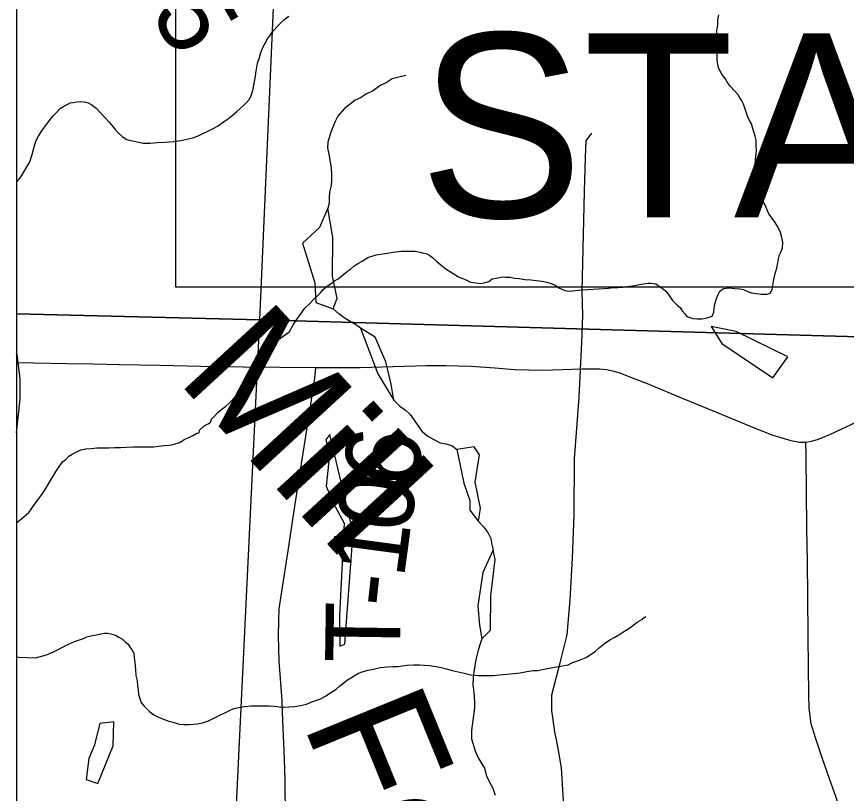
# Model space of a CAD drawing. Extents: x -6.1 to 38, y -7.7 to 22.
# Drawn here: x 2.1 to 2.73, y 16.715 to 17.306 of the extents above; entities that cross this region are included whole.
import ezdxf

# ---------------------------------------------------------------- set-up
doc = ezdxf.new("R2010")
doc.units = 0
for name, color, linetype in [('GM_X_Corporation', 7, 'Continuous'), ('GM_X_Minor_Lake', 7, 'Continuous'), ('GM_X_Minor_River', 7, 'Continuous'), ('GM_X_Minor_River_Text', 7, 'Continuous'), ('GM_X_State_Route', 7, 'Continuous'), ('GM_X_Township_Road', 7, 'Continuous'), ('GM_X_Township_Road_Text', 7, 'Continuous'), ('SH_Data', 7, 'Continuous'), ('SH_Text', 7, 'Continuous')]:
    doc.layers.add(name, color=color, linetype=linetype)

msp = doc.modelspace()

# ---------------------------------------------------------------- linework, layer by layer
at = {"layer": 'GM_X_Corporation'}
for points in [[(2.1, 20.09414), (2.1, 15.06368), (2.27273, 15.0594), (2.84159, 15.04746)], [(2.1, 19.36551), (2.1, 14.52316), (2.69973, 14.52546), (2.99532, 14.5306)]]:
    msp.add_lwpolyline(points, dxfattribs=at)
for points in [[(2.1, 18.08314), (2.1, 17.07982), (2.28477, 17.07512), (2.32853, 18.07616)], [(3.27494, 18.04606), (3.26971, 17.73075), (3.25731, 17.04745), (2.28477, 17.07512), (2.32853, 18.07616)], [(2.1, 17.07982), (2.1, 16.07221), (2.23638, 16.06946), (2.28477, 17.07512)], [(2.28477, 17.07512), (3.25731, 17.04745), (3.25716, 17.0301), (3.24834, 16.45211), (3.24267, 16.03673), (2.23638, 16.06946)]]:
    msp.add_lwpolyline(points, close=True, dxfattribs=at)
at = {"layer": 'GM_X_Minor_Lake'}
for points in [[(2.33637, 17.16011), (2.33002, 17.1453), (2.31723, 17.1335), (2.32644, 17.10322), (2.32727, 17.08844), (2.34051, 17.08357)], [(2.34051, 17.08357), (2.3435, 17.09154), (2.34002, 17.1082), (2.34025, 17.13776), (2.33637, 17.16011)], [(2.36136, 17.06887), (2.37438, 17.03406), (2.38656, 17.01402)], [(2.38656, 17.01402), (2.38462, 17.02614), (2.38038, 17.04318), (2.37235, 17.0621), (2.36136, 17.06887)], [(2.68601, 17.04709), (2.64663, 17.06626), (2.62772, 17.06997), (2.63572, 17.05712)], [(2.63572, 17.05712), (2.67438, 17.03113), (2.68601, 17.04709)], [(2.33795, 16.98805), (2.33495, 16.98387), (2.33765, 16.97251), (2.33512, 16.94863), (2.34047, 16.93614), (2.34885, 16.92064), (2.34541, 16.85051), (2.34553, 16.82701)], [(2.34553, 16.82701), (2.3493, 16.82855), (2.35569, 16.91346), (2.33795, 16.98805)], [(2.45086, 16.92181), (2.45232, 16.93205), (2.44845, 16.95174), (2.45175, 16.9726), (2.44756, 16.97865), (2.43435, 16.9767)], [(2.43435, 16.9767), (2.43976, 16.95095), (2.44436, 16.93771), (2.44439, 16.9305), (2.45086, 16.92181)], [(2.46192, 16.90026), (2.45407, 16.88317), (2.45041, 16.85776), (2.45162, 16.84299), (2.45355, 16.83276)], [(2.45355, 16.83276), (2.45994, 16.83923), (2.4602, 16.86538), (2.46346, 16.89306), (2.46192, 16.90026)], [(2.16333, 16.76829), (2.15888, 16.75122), (2.15477, 16.74173), (2.15296, 16.7258), (2.16166, 16.7228)], [(2.16166, 16.7228), (2.17324, 16.75128), (2.1739, 16.76947), (2.16333, 16.76829)]]:
    msp.add_lwpolyline(points, dxfattribs=at)
at = {"layer": 'GM_X_Minor_River'}
for points in [[(2.14607, 17.24083), (2.14873, 17.24124), (2.1514, 17.24089), (2.15444, 17.24015), (2.15712, 17.23866), (2.16057, 17.23603), (2.16365, 17.23264), (2.16673, 17.22925), (2.17058, 17.22511), (2.1729, 17.22247), (2.17483, 17.21983), (2.17714, 17.21719), (2.18021, 17.21456), (2.18366, 17.21231), (2.19624, 17.20939), (2.20156, 17.20945), (2.20687, 17.20988), (2.21257, 17.21032), (2.21979, 17.21077), (2.22472, 17.21158), (2.22928, 17.21238), (2.23382, 17.21357), (2.23799, 17.21513), (2.24139, 17.21669), (2.24517, 17.21862), (2.24933, 17.22057), (2.25311, 17.22251), (2.2565, 17.2252), (2.25989, 17.22752), (2.26366, 17.2306), (2.26705, 17.23329), (2.27006, 17.23598), (2.27269, 17.23829), (2.27495, 17.24059), (2.27682, 17.24289), (2.27831, 17.24557), (2.27941, 17.24938), (2.28012, 17.25357), (2.2812, 17.25891), (2.2819, 17.26424), (2.28297, 17.27033), (2.28444, 17.27453), (2.28553, 17.27834), (2.28701, 17.28216), (2.28887, 17.2856), (2.29073, 17.28866), (2.29298, 17.29172), (2.29522, 17.29517), (2.2986, 17.299), (2.30274, 17.30285), (2.30688, 17.30593)], [(2.61138, 17.07702), (2.61367, 17.07629), (2.61709, 17.07594), (2.62051, 17.07597), (2.62355, 17.07638), (2.6262, 17.07717), (2.62847, 17.07795), (2.62958, 17.08101), (2.63028, 17.08596), (2.63174, 17.09129), (2.63285, 17.09435), (2.63433, 17.09702), (2.63697, 17.09895), (2.64153, 17.09938), (2.64572, 17.09904), (2.64952, 17.09869), (2.65219, 17.09834), (2.65601, 17.09648), (2.6583, 17.09574), (2.66554, 17.09467), (2.66782, 17.09469), (2.6701, 17.09472), (2.67237, 17.0955), (2.67386, 17.09818), (2.67458, 17.10122), (2.67529, 17.1058), (2.67638, 17.11037), (2.67747, 17.11456), (2.67818, 17.11837), (2.67891, 17.12142), (2.67964, 17.12447), (2.68074, 17.12714), (2.68186, 17.12981), (2.68219, 17.134), (2.68138, 17.13779), (2.6802, 17.14158), (2.67825, 17.14575), (2.67631, 17.14915), (2.6736, 17.15292), (2.67128, 17.15632), (2.66933, 17.16049), (2.66699, 17.16579), (2.66502, 17.17223), (2.66264, 17.18057), (2.66143, 17.18626), (2.66101, 17.19006), (2.66097, 17.19348), (2.66131, 17.19653), (2.66166, 17.19957), (2.66199, 17.20338), (2.66194, 17.20794), (2.6619, 17.21174), (2.6611, 17.21478), (2.65991, 17.21895), (2.65833, 17.22426), (2.65639, 17.22728), (2.65522, 17.22993), (2.65443, 17.23258), (2.65325, 17.23599), (2.65208, 17.23902), (2.6509, 17.24167), (2.64936, 17.24394), (2.64819, 17.2462), (2.64242, 17.25261), (2.6401, 17.25563), (2.63855, 17.25828), (2.637, 17.26016), (2.63546, 17.26243), (2.63429, 17.2647), (2.63313, 17.26697), (2.63272, 17.26925), (2.6323, 17.27228), (2.63224, 17.27798), (2.63257, 17.28255), (2.63214, 17.28635), (2.6321, 17.28977), (2.63207, 17.29281), (2.63204, 17.29547), (2.63239, 17.29738), (2.63274, 17.30004), (2.63272, 17.30232), (2.63307, 17.30461), (2.63342, 17.30689)], [(2.39558, 17.26078), (2.39029, 17.25962), (2.38539, 17.25846), (2.38087, 17.25541), (2.37672, 17.2535), (2.37032, 17.24893), (2.36579, 17.24702), (2.36128, 17.24396), (2.35713, 17.24205), (2.34885, 17.23558), (2.34397, 17.22987), (2.34172, 17.22531), (2.33873, 17.21772), (2.3365, 17.21013), (2.33614, 17.20596), (2.3373, 17.20104), (2.33808, 17.19687), (2.33886, 17.19043), (2.33926, 17.18627), (2.33929, 17.18134), (2.33893, 17.17717), (2.33782, 17.17224), (2.33746, 17.16807), (2.33748, 17.1639), (2.33637, 17.16011)], [(2.1, 17.1799), (2.10002, 17.17992), (2.10302, 17.18337), (2.106, 17.18834), (2.11011, 17.19523), (2.11194, 17.20095), (2.11339, 17.20667), (2.11449, 17.21086), (2.11672, 17.21469), (2.11858, 17.21813), (2.12121, 17.22158), (2.1242, 17.22579), (2.12757, 17.23), (2.13057, 17.23308), (2.13321, 17.23576), (2.13584, 17.23769), (2.13849, 17.23886), (2.14076, 17.24002), (2.14304, 17.24042), (2.14607, 17.24083)], [(2.26539, 17.01579), (2.26727, 17.01733), (2.26877, 17.01925), (2.27026, 17.02154), (2.27175, 17.02422), (2.27361, 17.02766), (2.27548, 17.03034), (2.27735, 17.0334), (2.27921, 17.03684), (2.28183, 17.04067), (2.28482, 17.0445), (2.28857, 17.0491), (2.29232, 17.05332), (2.29607, 17.05754), (2.29984, 17.06062), (2.30286, 17.06293), (2.30549, 17.06486), (2.30738, 17.0664), (2.30998, 17.07137), (2.3126, 17.07519), (2.31597, 17.07979), (2.31896, 17.084), (2.32272, 17.08746), (2.32572, 17.09091), (2.32836, 17.09322), (2.33061, 17.09552), (2.33286, 17.09821), (2.33625, 17.1009), (2.33889, 17.10283), (2.34153, 17.10476), (2.34417, 17.1063), (2.35133, 17.11208), (2.35359, 17.11362), (2.35622, 17.11593), (2.35924, 17.11786), (2.36264, 17.11979), (2.36679, 17.1225), (2.37323, 17.12446), (2.37968, 17.12567), (2.38613, 17.12649), (2.39221, 17.12731), (2.39791, 17.12737), (2.40285, 17.12742), (2.40666, 17.1267), (2.40933, 17.12596), (2.41162, 17.12523), (2.41391, 17.12411), (2.41583, 17.12261), (2.41929, 17.1196), (2.42236, 17.11697), (2.42619, 17.11396), (2.43079, 17.11097), (2.43577, 17.10797), (2.44074, 17.10574), (2.44494, 17.10388), (2.44875, 17.10316), (2.45255, 17.10282), (2.45597, 17.10361), (2.45862, 17.1044), (2.46126, 17.10633), (2.46581, 17.10713), (2.46884, 17.10793), (2.47151, 17.10757), (2.47493, 17.1076), (2.47836, 17.10688), (2.48178, 17.10653), (2.48597, 17.10581), (2.49054, 17.10548), (2.49472, 17.10514), (2.49929, 17.10443), (2.50272, 17.1037), (2.50692, 17.1026), (2.50921, 17.10148), (2.5119, 17.09961), (2.51648, 17.09737), (2.51991, 17.09703), (2.52447, 17.09745), (2.52902, 17.09788), (2.53396, 17.09831), (2.54954, 17.09922), (2.55333, 17.09964), (2.55675, 17.09967), (2.56055, 17.10009), (2.56397, 17.10051), (2.56776, 17.10092), (2.57194, 17.10172), (2.57611, 17.10253), (2.5799, 17.10295), (2.58218, 17.10297), (2.58561, 17.10262), (2.58906, 17.09999), (2.59136, 17.0985), (2.59328, 17.097), (2.59521, 17.09435), (2.5983, 17.08982), (2.60176, 17.08643), (2.60407, 17.08456), (2.60562, 17.08191), (2.60754, 17.07965), (2.60909, 17.07776), (2.61138, 17.07702)], [(2.36136, 17.06887), (2.35757, 17.07151), (2.35341, 17.07377), (2.34886, 17.07678), (2.34469, 17.07979), (2.34051, 17.08357)], [(2.1, 16.92078), (2.10563, 16.92561), (2.1094, 16.92869), (2.11239, 16.9329), (2.11575, 16.9375), (2.11912, 16.94247), (2.12211, 16.94707), (2.12472, 16.95128), (2.12733, 16.95548), (2.12994, 16.96007), (2.13293, 16.96429), (2.13518, 16.96735), (2.13744, 16.96889), (2.13969, 16.97158), (2.14233, 16.97312), (2.14536, 16.97467), (2.14876, 16.97623), (2.15255, 16.97703), (2.15673, 16.97745), (2.1609, 16.97787), (2.16547, 16.97792), (2.17003, 16.97796), (2.17459, 16.97801), (2.17915, 16.97805), (2.18333, 16.97847), (2.18865, 16.97853), (2.19283, 16.97857), (2.19663, 16.97861), (2.20005, 16.97864), (2.20423, 16.97868), (2.20803, 16.9791), (2.21221, 16.97952), (2.216, 16.97994), (2.21904, 16.98035), (2.22131, 16.98113), (2.22396, 16.98192), (2.22736, 16.98423), (2.23076, 16.98579), (2.23379, 16.98734), (2.23681, 16.98889), (2.2387, 16.98929), (2.23906, 16.99119), (2.24244, 16.99465), (2.24547, 16.9962), (2.24735, 16.99736), (2.24809, 16.99965), (2.25034, 17.00195), (2.25297, 17.00464), (2.25598, 17.00733), (2.259, 17.00964), (2.26125, 17.01157), (2.26313, 17.01349), (2.26539, 17.01579)], [(2.38656, 17.01402), (2.39112, 17.00949), (2.39529, 17.00686), (2.39908, 17.00308), (2.40213, 16.99892), (2.40783, 16.99061), (2.41239, 16.98684), (2.41693, 16.98421), (2.42186, 16.98157), (2.42602, 16.98083), (2.43056, 16.97972), (2.43435, 16.9767)], [(2.45086, 16.92181), (2.45503, 16.91766), (2.45808, 16.9135), (2.46036, 16.90897), (2.46114, 16.90442), (2.46192, 16.90026)], [(2.33869, 16.79182), (2.34247, 16.79413), (2.34548, 16.79683), (2.34849, 16.79914), (2.3515, 16.80145), (2.35452, 16.80338), (2.35717, 16.80493), (2.35981, 16.80647), (2.36246, 16.80764), (2.36701, 16.80883), (2.37118, 16.80963), (2.37649, 16.81082), (2.3818, 16.81126), (2.38598, 16.81168), (2.38978, 16.81171), (2.39282, 16.81212), (2.39661, 16.81254), (2.40155, 16.81297), (2.40611, 16.81302), (2.40992, 16.81267), (2.41372, 16.81233), (2.41867, 16.81162), (2.42249, 16.8109), (2.42668, 16.8098), (2.43087, 16.8087), (2.43545, 16.80761), (2.44002, 16.80651), (2.44498, 16.80542), (2.45031, 16.80471), (2.45601, 16.80477), (2.46209, 16.80483), (2.48259, 16.80694), (2.48753, 16.80774), (2.49246, 16.80855), (2.49588, 16.80859), (2.49816, 16.80899), (2.50195, 16.80979), (2.50612, 16.81059), (2.50991, 16.81139), (2.51485, 16.8122), (2.51902, 16.813), (2.52242, 16.81455), (2.52772, 16.81651), (2.53264, 16.81846), (2.53604, 16.82077), (2.53943, 16.82309), (2.54282, 16.82616), (2.54658, 16.82924), (2.55073, 16.83194), (2.55451, 16.83388), (2.55753, 16.83581), (2.56055, 16.83775), (2.56432, 16.84006), (2.56809, 16.84276), (2.57149, 16.84546), (2.57488, 16.84739), (2.57677, 16.84893), (2.5779, 16.8497)], [(2.1, 16.81903), (2.10155, 16.81873), (2.11448, 16.8181), (2.12281, 16.82047), (2.12811, 16.8228), (2.13944, 16.82861), (2.14399, 16.83056), (2.1508, 16.83291), (2.15345, 16.83408), (2.15648, 16.83487), (2.16065, 16.83567), (2.16407, 16.83646), (2.16672, 16.83687), (2.16938, 16.8369), (2.17167, 16.83654), (2.1751, 16.83543), (2.17778, 16.83394), (2.18046, 16.83244), (2.18277, 16.83019), (2.18468, 16.82868), (2.18623, 16.82604), (2.18778, 16.82415), (2.18894, 16.82188), (2.18936, 16.81884), (2.18979, 16.81467), (2.19023, 16.80935), (2.19066, 16.80479), (2.19147, 16.80062), (2.1919, 16.79682), (2.19231, 16.79378), (2.19273, 16.79036), (2.19353, 16.78733), (2.1947, 16.7843), (2.19663, 16.78166), (2.20125, 16.77714), (2.20432, 16.77489), (2.20776, 16.77302), (2.21157, 16.77154), (2.21577, 16.77006), (2.21959, 16.76896), (2.2234, 16.76786), (2.22721, 16.76751), (2.23139, 16.76755), (2.23709, 16.76799), (2.24126, 16.76879), (2.2458, 16.77036), (2.25034, 16.77269), (2.26168, 16.77812), (2.26508, 16.77968), (2.26887, 16.78047), (2.27305, 16.78128), (2.27799, 16.7817), (2.28407, 16.78177), (2.28825, 16.78181), (2.29205, 16.78185), (2.29509, 16.7815), (2.29814, 16.78115), (2.30042, 16.78079), (2.30308, 16.78082), (2.30689, 16.78085), (2.31144, 16.78128), (2.31561, 16.78208), (2.32017, 16.78289), (2.32433, 16.78483), (2.33039, 16.78679), (2.33454, 16.78911), (2.33869, 16.79182)], [(2.45355, 16.83276), (2.45206, 16.82897), (2.45057, 16.82403), (2.44909, 16.81796), (2.44836, 16.81379), (2.44725, 16.80735), (2.4469, 16.80317), (2.44654, 16.79787), (2.44733, 16.79181), (2.44774, 16.78499), (2.44776, 16.78044), (2.4474, 16.77627), (2.44631, 16.76869), (2.44558, 16.763), (2.44561, 16.75656), (2.4483, 16.74747), (2.45059, 16.74217), (2.45554, 16.73424), (2.45708, 16.72856), (2.45937, 16.72364), (2.46166, 16.7191), (2.46357, 16.7138)]]:
    msp.add_lwpolyline(points, dxfattribs=at)
at = {"layer": 'GM_X_State_Route'}
msp.add_lwpolyline([(2.1, 16.9893), (2.10279, 17.01486), (2.10279, 17.03047), (2.10044, 17.04844), (2.1, 17.04974)], dxfattribs=at)
at = {"layer": 'GM_X_Township_Road'}
for points in [[(2.51613, 16.69726), (2.51388, 16.73472), (2.51121, 16.75089), (2.50896, 16.76194), (2.50671, 16.77831), (2.50651, 16.78997), (2.51306, 16.81453), (2.51817, 16.83582), (2.52063, 16.86221), (2.52227, 16.89393), (2.5235, 16.92709), (2.5239, 16.96945), (2.52738, 17.01611), (2.52946, 17.05822), (2.53018, 17.0788), (2.5297, 17.09676), (2.53138, 17.17265), (2.53221, 17.19868), (2.53281, 17.2112), (2.53688, 17.21695)], [(2.1, 17.04264), (2.11287, 17.04245), (2.13836, 17.04206), (2.15814, 17.04167), (2.17793, 17.04127), (2.20899, 17.04066), (2.24005, 17.04004), (2.25621, 17.03972), (2.27236, 17.0394), (2.29988, 17.03922), (2.32741, 17.03905), (2.34425, 17.03895), (2.3611, 17.03885), (2.38618, 17.03967), (2.41127, 17.0405), (2.42618, 17.04037), (2.44532, 17.03991), (2.46329, 17.03857), (2.47829, 17.03738), (2.50013, 17.03699), (2.52947, 17.03803), (2.54283, 17.03796), (2.5483, 17.03731), (2.5537, 17.03607), (2.55827, 17.03481), (2.56393, 17.03254), (2.57906, 17.0268), (2.60565, 17.01571), (2.63224, 17.00461), (2.66032, 16.99312), (2.67454, 16.98748), (2.68813, 16.98352), (2.6947, 16.98215), (2.69965, 16.98221), (2.70486, 16.98306), (2.70909, 16.98455), (2.71825, 16.98827), (2.74644, 17.00133)], [(2.30431, 16.69562), (2.30405, 16.72585), (2.30316, 16.74796), (2.30226, 16.77007), (2.3017, 16.78576), (2.29936, 16.8158), (2.29891, 16.83487), (2.29909, 16.84644), (2.29944, 16.8555), (2.30144, 16.86874), (2.3062, 16.89944), (2.31096, 16.93014), (2.31572, 16.96084), (2.32047, 16.99155), (2.3235, 17.01108), (2.32652, 17.03061), (2.32741, 17.03905)], [(2.75208, 16.64968), (2.74739, 16.65274), (2.7429, 16.6571), (2.73984, 16.66309), (2.73554, 16.67495), (2.72776, 16.69717), (2.72253, 16.71211), (2.7173, 16.72705), (2.71206, 16.74219), (2.70682, 16.75733), (2.70363, 16.76795), (2.70252, 16.77602), (2.702, 16.78006), (2.70192, 16.7897), (2.70163, 16.81194), (2.70135, 16.83418), (2.701, 16.86525), (2.70072, 16.89097), (2.70043, 16.9167), (2.70008, 16.94437), (2.69972, 16.97205), (2.69965, 16.98221)]]:
    msp.add_lwpolyline(points, dxfattribs=at)
at = {"layer": 'SH_Data'}
msp.add_line((2.1, 20.9), (2.1, 14.1), dxfattribs=at)
at = {"layer": 'SH_Text'}
msp.add_lwpolyline([(2.22089, 17.76448), (4.05377, 17.76448), (4.05377, 17.09999), (2.22089, 17.09999)], close=True, dxfattribs=at)

# ---------------------------------------------------------------- texts
at = {"layer": 'GM_X_Minor_River_Text'}
for s, height, rotation, p in [('Mill', 0.0947, 312.6449, (2.22046, 17.03006)), ('Fork', 0.094697, 292.18897, (2.31691, 16.7689))]:
    msp.add_text(s, height=height, rotation=rotation, dxfattribs=at).set_placement(p)
at = {"layer": 'GM_X_Township_Road_Text'}
for s, rotation, p in [('5', 299.21746, (2.20117, 17.3092)), ('6', 81.95692, (2.40356, 16.94637)), ('0', 82.02231, (2.39874, 16.91201)), ('1', 82.37964, (2.39415, 16.87769)), ('-', 83.61877, (2.39162, 16.85503)), ('T', 89.16283, (2.39109, 16.81406))]:
    msp.add_text(s, height=0.05682, rotation=rotation, dxfattribs=at).set_placement(p)
at = {"layer": 'SH_Text'}
msp.add_text('STA. 306+50.00', height=0.1399997, dxfattribs=at).set_placement((2.40563, 17.15302))

doc.saveas('drawing.dxf')
